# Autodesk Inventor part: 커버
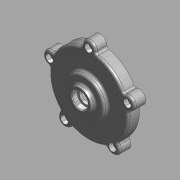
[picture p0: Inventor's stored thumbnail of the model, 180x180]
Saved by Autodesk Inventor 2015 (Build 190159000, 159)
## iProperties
Created: 2015-11
Part Number: 커버
Document SubType Name: 모델링
Designer: mdu
Material: 알루미늄 6061
Density: 2.71 g/cm^3
Appearance: 알루미늄 캐스트
Mass: 201.189 g
Surface Area: 286.328 cm^2
Volume: 74.2394 cm^3
변환 표준: STEP AP214IS
파일 이름: C:\Users\SeoGD\Desktop\?쒗뿕\而ㅻ쾭-1.stp
전처리기: Build: 253, Release: 2010 SP1 - Date: Wed 07/29/2009
전송 단위: 밀리미터
불확실성: 0.01
Author: mdu
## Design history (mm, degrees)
sketch "스케치1"
  geometry: L1 (0, 0)-(0, 26); L2 (50, 0)-(50, 15); L3 (50, 15)-(25, 15); L4 (25, 15)-(25, 21); L5 (25, 21)-(15, 21); L6 (15, 21)-(13.66, 26); L7 (13.66, 26)-(10, 26); L8 (50, 0)-(45, 0); L9 (45, 0)-(45, 10); L10 (45, 10)-(14.5, 10); L11 (14.5, 10)-(13.266, 3); L12 (13.266, 3)-(11, 3); L13 (11, 3)-(11, 16); L14 (11, 16)-(7.5, 16); L15 (7.5, 16)-(7.5, 19); L16 (7.5, 19)-(10, 19); L17 (10, 19)-(10, 26)
  constraints: 34 end point, 10 parallel, 2 perpendicular, 2 point on line, 1 vertical
  dimensions: "d11" = 100 diameter of L2 L1; "d12" = 22 diameter of L13 L1; "d13" = 90 diameter of L9 L1; "d14" = 15 distance between parallel lines of L3 L8; "d15" = 10 distance between parallel lines of L8 L10; "d16" = 29 diameter of L10.end L1; "d17" = 100 deg angle of L11 L10; "d18" = 7 distance between parallel lines of L12 L10; "d19" = 13 distance between parallel lines of L14 L12; "d20" = 3 distance between parallel lines of L16 L14; "d21" = 15 diameter of L15 L1; "d22" = 20 diameter of L17 L1; "d23" = 30 diameter of L5.end L1; "d24" = 6 distance between parallel lines of L5 L3; "d25" = 50 diameter of L4 L1; "d26" = 105 deg angle of L5 L6; "d50" = 26 distance of L1.start L1.end
revolve "회전1" sketch "스케치1" stored, may be unused: angle "d27" = 90 deg
sketch "스케치2" dims "d29" = 104
  geometry: A1 r 8.5 centre (0, 52) between (8.074, 49.344) and (-8.074, 49.344); A2 r 50 centre (0, 0) between (-8.074, 49.344) and (8.074, 49.344) reference; 2 further points
  constraints: 4 point on circle, 2 vertical alignment, 1 centre point, 1 coincident, 2 other
  dimensions: "d28" = 17 diameter of A1
extrude "돌출1" join sketch "스케치2" stored distance "d30" = 10; taper "d31" = 0 deg
fillet "모깎기3" dims "d32" = 3
fillet "모깎기4" dims "d45" = 3, "d46" = 0.2
chamfer "모따기1" distance "d47" = 1; stored, may be unused: second distance "d48" = 2, angle "d49" = 45 deg
hole "구멍2" diameter "d38" = 5.5; stored, may be unused: countersink angle "d42" = 90 deg, drill point angle "d44" = 118 deg; dims "d36" = 10, "d37" = 10, "d39" = 6, "d40" = 9.5, "d41" = 5.4, "d43" = 8
node "솔리드1"
node "솔리드 본체"
node "곡면 본체"
pattern_circular "원형 패턴1" dims angle "d34" = 360 deg
pattern_circular "원형 패턴2" dims angle "d52" = 360 deg
node "솔리드2"
